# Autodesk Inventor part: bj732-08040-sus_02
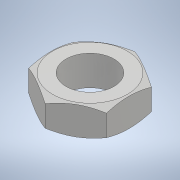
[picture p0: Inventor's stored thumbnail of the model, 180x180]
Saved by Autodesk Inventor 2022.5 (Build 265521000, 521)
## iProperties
Part Number: bj732-08040-sus_02
Material: 一般
Document SubType Name: Modeling
Designer: ImaoCorp
Density: 1 g/cm^3
Appearance: 既定
Author: ImaoCorp
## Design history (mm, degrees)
feature "bj732-08040-sus_02"
node "ソリッド1"
